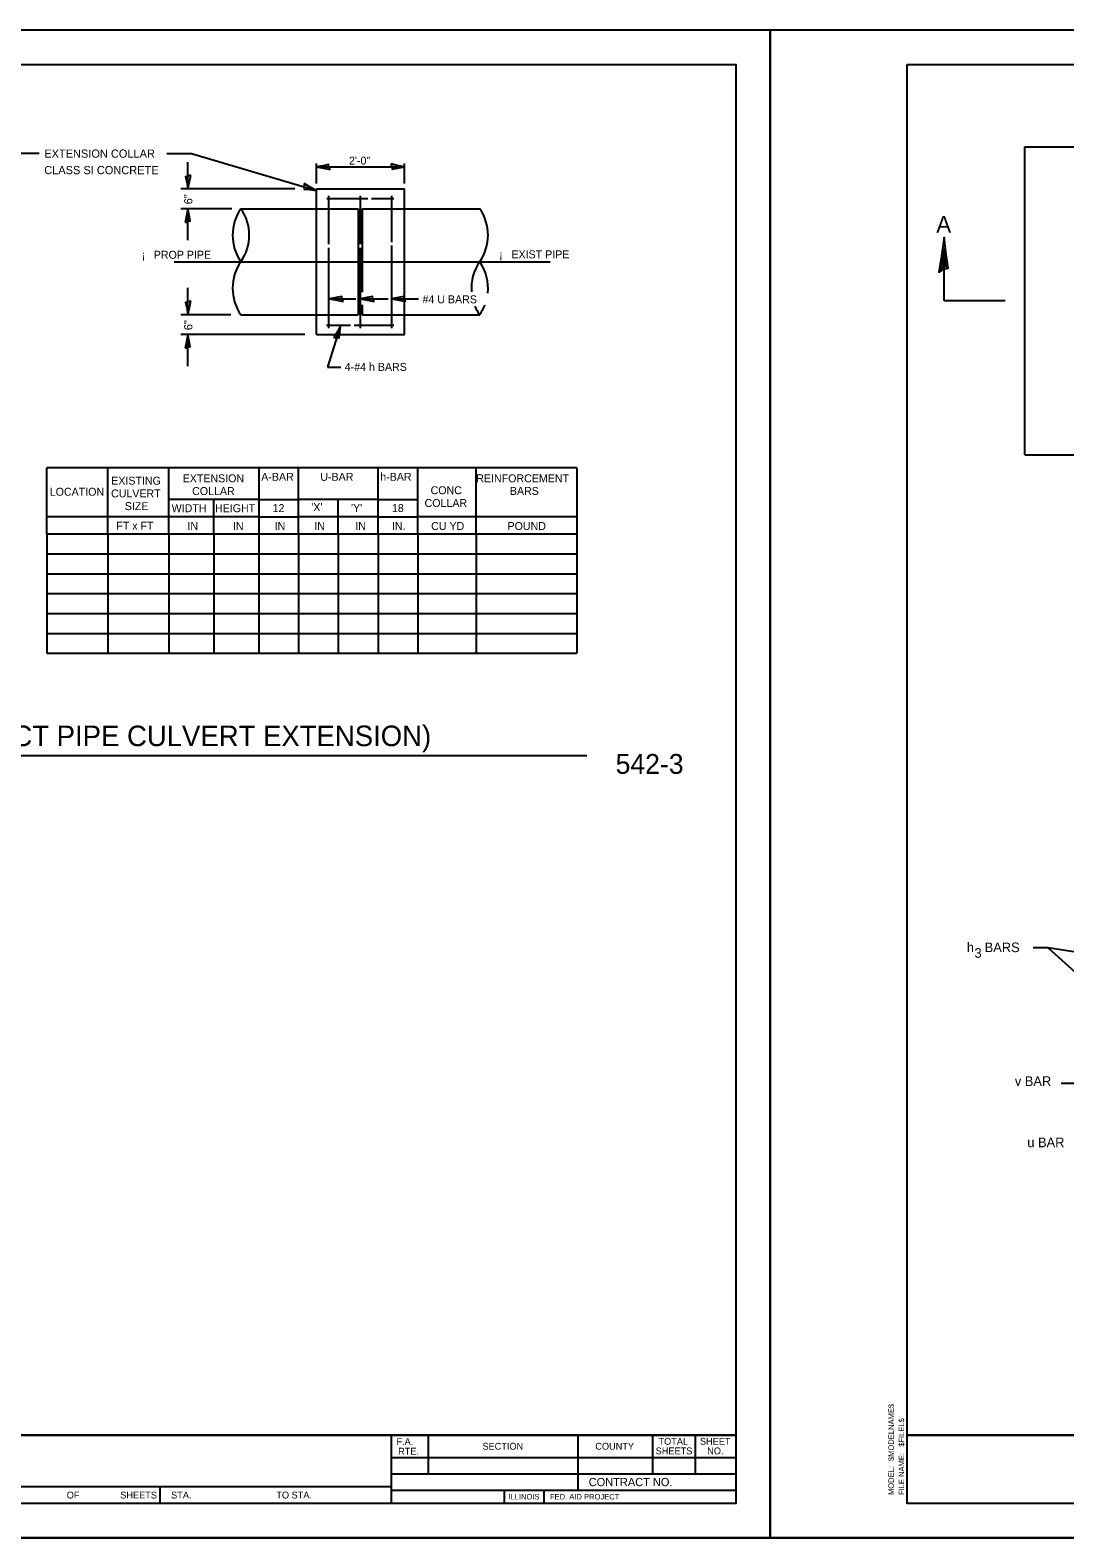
# Model space of a CAD drawing. Extents: x 2133490 to 2172050, y 2138301 to 2145980.
# Drawn here: x 2138050 to 2138805, y 2141438 to 2142538 of the extents above; entities that cross this region are included whole.
import ezdxf

# ---------------------------------------------------------------- set-up
doc = ezdxf.new("R2010")
doc.units = 0
for name, color, linetype in [('Level 1', 7, 'Continuous'), ('Level 23', 7, 'Continuous'), ('Level 40', 7, 'Continuous'), ('Level 63', 7, 'Continuous'), ('ROW_PR_Notes', 7, 'Continuous'), ('Sheets_50 Reference Boundary', 7, 'Continuous'), ('Sheets_General Details', 7, 'Continuous'), ('Sheets_Printer Plotting Border', 7, 'Continuous')]:
    doc.layers.add(name, color=color, linetype=linetype)

msp = doc.modelspace()

# ---------------------------------------------------------------- linework, layer by layer
at = {"layer": 'Level 23'}
for p, q in [((2138062.3, 2142170), (2138062.3, 2142218.3)), ((2138448.7, 2142218.3), (2138062.3, 2142218.3)), ((2138106.7, 2142170), (2138106.7, 2142218.3)), ((2138151.2, 2142170), (2138151.2, 2142218.3)), ((2138151.2, 2142218.3), (2138151.2, 2142218.3)), ((2138216.8, 2142218.3), (2138216.8, 2142083)), ((2138245.8, 2142170), (2138245.8, 2142218.3)), ((2138245.8, 2142218.3), (2138245.8, 2142218.3)), ((2138303.8, 2142170), (2138303.8, 2142218.3)), ((2138332.8, 2142170), (2138332.8, 2142218.3)), ((2138375.3, 2142170), (2138375.3, 2142218.3)), ((2138448.7, 2142218.3), (2138448.7, 2142083)), ((2138216.8, 2142195.1), (2138151.2, 2142195.1)), ((2138216.8, 2142195.1), (2138245.8, 2142195.1)), ((2138303.8, 2142195.1), (2138245.8, 2142195.1)), ((2138274.8, 2142170), (2138274.8, 2142195.1)), ((2138303.8, 2142195.1), (2138332.8, 2142195.1)), ((2138184, 2142170), (2138184, 2142194.7)), ((2138151.2, 2142182.5), (2138062.6, 2142182.5)), ((2138216.8, 2142182.5), (2138151.2, 2142182.5)), ((2138216.8, 2142182.5), (2138245.8, 2142182.5)), ((2138303.8, 2142182.5), (2138245.8, 2142182.5)), ((2138303.8, 2142182.5), (2138332.8, 2142182.5)), ((2138448.7, 2142182.5), (2138332.8, 2142182.5)), ((2138062.3, 2142170), (2138062.3, 2142083)), ((2138063.1, 2142170), (2138151.2, 2142170)), ((2138106.7, 2142170), (2138106.7, 2142083)), ((2138151.2, 2142170), (2138151.2, 2142083)), ((2138151.2, 2142170), (2138151.2, 2142083)), ((2138151.2, 2142170), (2138216.8, 2142170)), ((2138184, 2142170.2), (2138184, 2142083)), ((2138216.8, 2142170), (2138245.8, 2142170)), ((2138245.8, 2142170.8), (2138245.8, 2142083)), ((2138245.8, 2142170), (2138303.8, 2142170)), ((2138274.8, 2142170), (2138274.8, 2142083)), ((2138303.8, 2142170), (2138303.8, 2142083)), ((2138303.8, 2142170), (2138332.8, 2142170)), ((2138332.8, 2142170), (2138332.8, 2142083)), ((2138332.8, 2142170), (2138448.7, 2142170)), ((2138375.3, 2142170), (2138375.3, 2142083)), ((2138061.7, 2142155.5), (2138151.2, 2142155.5)), ((2138151.2, 2142155.5), (2138216.8, 2142155.5)), ((2138216.8, 2142155.5), (2138245.8, 2142155.5)), ((2138245.8, 2142155.5), (2138303.8, 2142155.5)), ((2138303.8, 2142155.5), (2138332.8, 2142155.5)), ((2138332.8, 2142155.5), (2138448.7, 2142155.5)), ((2138063.1, 2142141), (2138151.2, 2142141)), ((2138151.2, 2142141), (2138216.8, 2142141)), ((2138216.8, 2142141), (2138245.8, 2142141)), ((2138245.8, 2142141), (2138303.8, 2142141)), ((2138303.8, 2142141), (2138332.8, 2142141)), ((2138332.8, 2142141), (2138448.7, 2142141)), ((2138062.6, 2142126.5), (2138151.2, 2142126.5)), ((2138151.2, 2142126.5), (2138216.8, 2142126.5)), ((2138216.8, 2142126.5), (2138245.8, 2142126.5)), ((2138245.8, 2142126.5), (2138303.8, 2142126.5)), ((2138303.8, 2142126.5), (2138332.8, 2142126.5)), ((2138332.8, 2142126.5), (2138448.7, 2142126.5)), ((2138062.2, 2142112), (2138151.2, 2142112)), ((2138151.2, 2142112), (2138216.8, 2142112)), ((2138216.8, 2142112), (2138245.8, 2142112)), ((2138245.8, 2142112), (2138303.8, 2142112)), ((2138303.8, 2142112), (2138332.8, 2142112)), ((2138332.8, 2142112), (2138448.7, 2142112)), ((2138062.6, 2142097.5), (2138151.2, 2142097.5)), ((2138151.2, 2142097.5), (2138216.8, 2142097.5)), ((2138216.8, 2142097.5), (2138245.8, 2142097.5)), ((2138245.8, 2142097.5), (2138303.8, 2142097.5)), ((2138303.8, 2142097.5), (2138332.8, 2142097.5)), ((2138332.8, 2142097.5), (2138448.7, 2142097.5)), ((2138062.3, 2142083), (2138151.2, 2142083)), ((2138151.2, 2142083), (2138216.8, 2142083)), ((2138216.8, 2142083), (2138245.8, 2142083)), ((2138245.8, 2142083), (2138303.8, 2142083)), ((2138303.8, 2142083), (2138332.8, 2142083)), ((2138332.8, 2142083), (2138448.7, 2142083))]:
    msp.add_line(p, q, dxfattribs=at)
at = {"layer": 'Level 40'}
for p, q in [((2138258.8, 2142407.3), (2138289.4, 2142407.3)), ((2138289.4, 2142407.3), (2138289.4, 2142330)), ((2138292.3, 2142407.3), (2138377.9, 2142407.3)), ((2138292.3, 2142407.3), (2138292.3, 2142346.3)), ((2138155.2, 2142368.6), (2138429.2, 2142368.6)), ((2138258.8, 2142330), (2138289.4, 2142330)), ((2138292.3, 2142337.1), (2138292.3, 2142330)), ((2138292.3, 2142330), (2138377.9, 2142330))]:
    msp.add_line(p, q, dxfattribs=at)
at = {"layer": 'Level 63'}
for p, q in [((2138056.8, 2142447.6), (2138041.2, 2142447.6)), ((2138149.8, 2142447.6), (2138167.7, 2142447.6)), ((2138165.2, 2142421.8), (2138165.2, 2142441.3)), ((2138167.7, 2142447.6), (2138258.8, 2142420.7)), ((2138258.8, 2142425.8), (2138258.8, 2142440.4)), ((2138258.8, 2142437.9), (2138323, 2142437.9)), ((2138323, 2142425.8), (2138323, 2142440.4)), ((2138243.1, 2142421.8), (2138160, 2142421.8)), ((2138197.2, 2142407.3), (2138160, 2142407.3)), ((2138165.2, 2142384.3), (2138165.2, 2142407.3)), ((2138165.2, 2142330), (2138165.2, 2142349.6)), ((2138196.4, 2142330), (2138160, 2142330)), ((2138276.5, 2142322), (2138266.9, 2142291.6)), ((2138250.5, 2142315.5), (2138160, 2142315.5)), ((2138165.2, 2142292.5), (2138165.2, 2142315.5)), ((2138266.9, 2142291.6), (2138276.7, 2142291.6))]:
    msp.add_line(p, q, dxfattribs=at)
for points in [[(2138268.8, 2142435.8), (2138268, 2142437.7), (2138267.7, 2142439.5), (2138263.8, 2142438.7), (2138258.8, 2142437.9), (2138264.1, 2142436.9)], [(2138313, 2142440), (2138313.8, 2142438), (2138314.1, 2142436.2), (2138318, 2142437), (2138323, 2142437.9), (2138317.6, 2142438.8)], [(2138167.3, 2142431.8), (2138165.4, 2142431), (2138163.5, 2142430.6), (2138164.3, 2142426.8), (2138165.2, 2142421.8), (2138166.2, 2142427.1)], [(2138249.8, 2142425.6), (2138250, 2142423.5), (2138249.8, 2142421.6), (2138253.7, 2142421.3), (2138258.8, 2142420.7), (2138253.9, 2142423.2)], [(2138163.1, 2142397.3), (2138165, 2142398.1), (2138166.9, 2142398.4), (2138166.1, 2142402.3), (2138165.2, 2142407.3), (2138164.2, 2142402)], [(2138167.3, 2142340), (2138165.4, 2142339.2), (2138163.5, 2142338.9), (2138164.3, 2142335), (2138165.2, 2142330), (2138166.2, 2142335.3)], [(2138278.4, 2142339.5), (2138277.6, 2142341.4), (2138277.3, 2142343.3), (2138273.4, 2142342.5), (2138268.4, 2142341.6), (2138273.7, 2142340.6)], [(2138300.9, 2142339.5), (2138300.1, 2142341.4), (2138299.8, 2142343.3), (2138295.9, 2142342.5), (2138290.9, 2142341.6), (2138296.2, 2142340.6)], [(2138323.8, 2142339.5), (2138323, 2142341.4), (2138322.7, 2142343.3), (2138318.8, 2142342.5), (2138313.8, 2142341.6), (2138319.1, 2142340.6)], [(2138271.5, 2142313.1), (2138273.6, 2142313.3), (2138275.4, 2142313), (2138275.8, 2142317), (2138276.5, 2142322), (2138274, 2142317.2)], [(2138163.1, 2142305.5), (2138165, 2142306.3), (2138166.9, 2142306.7), (2138166.1, 2142310.5), (2138165.2, 2142315.5), (2138164.2, 2142310.2)]]:
    msp.add_lwpolyline(points, close=True, dxfattribs=at)
at = {"layer": 'ROW_PR_Notes'}
for p, q in [((2138775.4, 2142227.7), (2138775.4, 2142452.4)), ((2138775.4, 2142452.4), (2139621.5, 2142452.4)), ((2138258.8, 2142421.8), (2138323, 2142421.8)), ((2138258.8, 2142315.5), (2138258.8, 2142421.8)), ((2138268, 2142381.5), (2138268, 2142416.7)), ((2138290.9, 2142381.5), (2138290.9, 2142416.7)), ((2138313.8, 2142382.9), (2138313.8, 2142416.7)), ((2138323, 2142315.5), (2138323, 2142421.8)), ((2138203.8, 2142407.3), (2138258.8, 2142407.3)), ((2138266.5, 2142414.7), (2138296.4, 2142414.7)), ((2138299, 2142414.7), (2138315.3, 2142414.7)), ((2138268, 2142320.2), (2138268, 2142378.7)), ((2138290.9, 2142320.2), (2138290.9, 2142378.7)), ((2138313.8, 2142320.2), (2138313.8, 2142380.5)), ((2138716.5, 2142340.1), (2138716.5, 2142377.9)), ((2138268.4, 2142341.6), (2138287.7, 2142341.6)), ((2138290.9, 2142341.6), (2138311.2, 2142341.6)), ((2138313.8, 2142341.6), (2138333.3, 2142341.6)), ((2138761.1, 2142340.1), (2138716.5, 2142340.1)), ((2138203.8, 2142330), (2138258.8, 2142330)), ((2138266.1, 2142322.4), (2138283.7, 2142322.4)), ((2138286.3, 2142322.4), (2138315.3, 2142322.4)), ((2138258.8, 2142315.5), (2138323, 2142315.5)), ((2138775.4, 2142227.7), (2139621.5, 2142227.7)), ((2137804.4, 2142008.4), (2138455.9, 2142008.4)), ((2138792.3, 2141868.1), (2138781.4, 2141868.1)), ((2138853.2, 2141858.6), (2138792.3, 2141868.1)), ((2138792.3, 2141868.1), (2138854.1, 2141812.4)), ((2138823.4, 2141769.1), (2138802, 2141769.1))]:
    msp.add_line(p, q, dxfattribs=at)
msp.add_lwpolyline([(2138716.2, 2142363.2), (2138719.6, 2142364), (2138718.1, 2142373.8), (2138716.5, 2142386.4), (2138714.6, 2142372.9), (2138712.6, 2142361.1), (2138716.2, 2142363.2), (2138718.5, 2142364.2), (2138716.5, 2142377.9), (2138713.8, 2142362.9), (2138716.8, 2142365.2), (2138716.4, 2142371.5), (2138715.5, 2142365.4)], dxfattribs=at)
for centre, start, end in [((2138231.5, 2142388), 145.1049, 214.8951), ((2138176.1, 2142388), 325.1049, 34.8951), ((2138350.2, 2142388), 325.1049, 34.8951), ((2138231.5, 2142349.3), 145.1049, 214.8951), ((2138405.6, 2142349.3), 145.1049, 184.4399), ((2138350.2, 2142349.3), 353.7279, 34.8951), ((2138405.6, 2142349.3), 202.8569, 214.8951), ((2138350.2, 2142349.3), 325.1049, 338.936)]:
    msp.add_arc(centre, 33.8, start, end, dxfattribs=at)
at = {"layer": 'Sheets_50 Reference Boundary'}
for points in [[(2136989.7, 2142512.6), (2138564.7, 2142512.6), (2138564.7, 2141512.6), (2136989.7, 2141512.6)], [(2138689.7, 2142512.6), (2140264.7, 2142512.6), (2140264.7, 2141512.6), (2138689.7, 2141512.6)]]:
    msp.add_lwpolyline(points, close=True, dxfattribs=at)
at = {"layer": 'Sheets_General Details'}
for p, q in [((2138589.7, 2142537.6), (2136889.7, 2142537.6)), ((2138589.7, 2142537.6), (2138589.7, 2141437.6)), ((2140289.7, 2142537.6), (2138589.7, 2142537.6)), ((2138589.7, 2141437.6), (2138589.7, 2142537.6)), ((2136989.7, 2141512.6), (2138564.7, 2141512.6)), ((2138313.4, 2141512.6), (2138313.4, 2141462.6)), ((2138340.4, 2141512.6), (2138340.4, 2141484.3)), ((2138449.4, 2141512.6), (2138449.4, 2141472.3)), ((2138504, 2141512.6), (2138504, 2141484.3)), ((2138535, 2141512.6), (2138535, 2141484.3)), ((2138689.7, 2141512.6), (2140264.7, 2141512.6)), ((2138313.4, 2141496.3), (2138564.7, 2141496.3)), ((2138313.4, 2141484.3), (2138564.7, 2141484.3)), ((2137928.4, 2141475.1), (2138313.4, 2141475.1)), ((2138144.7, 2141475.1), (2138144.7, 2141462.6)), ((2138313.4, 2141472.3), (2138564.7, 2141472.3)), ((2138395.7, 2141472.3), (2138395.7, 2141462.6)), ((2138424.7, 2141472.3), (2138424.7, 2141462.6)), ((2138589.7, 2141437.6), (2136889.7, 2141437.6)), ((2140289.7, 2141437.6), (2138589.7, 2141437.6))]:
    msp.add_line(p, q, dxfattribs=at)
for points in [[(2136989.7, 2142512.6), (2138564.7, 2142512.6), (2138564.7, 2141462.6), (2136989.7, 2141462.6)], [(2138689.7, 2142512.6), (2140264.7, 2142512.6), (2140264.7, 2141462.6), (2138689.7, 2141462.6)]]:
    msp.add_lwpolyline(points, close=True, dxfattribs=at)
at = {"layer": 'Sheets_Printer Plotting Border'}
for points in [[(2136889.7, 2141437.6), (2138589.7, 2141437.6), (2138589.7, 2142537.6), (2136889.7, 2142537.6)], [(2138589.7, 2141437.6), (2140289.7, 2141437.6), (2140289.7, 2142537.6), (2138589.7, 2142537.6)]]:
    msp.add_lwpolyline(points, close=True, dxfattribs=at)

# ---------------------------------------------------------------- texts
at = {"layer": 'Level 1'}
msp.add_text('542-3', height=14.49, dxfattribs=at).set_placement((2138477, 2141995))
at = {"layer": 'Level 23'}
for s, height, p in [('EXISTING', 5.8, (2138109.2, 2142206)), ('EXTENSION', 5.8, (2138161.3, 2142207.7)), ('A-BAR', 5.8, (2138218.6, 2142208.8)), ('U-BAR', 5.8, (2138261.7, 2142208.8)), ('h-BAR', 5.8, (2138305.4, 2142208.8)), ('REINFORCEMENT', 5.8, (2138375.4, 2142207.7)), ('LOCATION', 5.8, (2138064.4, 2142197.9)), ('CULVERT', 5.8, (2138109.1, 2142196.7)), ('COLLAR', 5.8, (2138168.2, 2142198.4)), ('COLLAR', 5.8, (2138337.7, 2142189.7)), ('CONC', 5.8, (2138342.1, 2142199)), ('BARS', 5.8, (2138399.9, 2142198.5)), ('SIZE', 5.8, (2138119.1, 2142187.4)), ('WIDTH', 5.8, (2138153.3, 2142185.9)), ('HEIGHT', 5.8, (2138184.9, 2142185.9)), ('12', 5.8, (2138226.9, 2142186)), ('12', 5.8, (2138226.9, 2142186)), ("'X'", 5.8, (2138255.1, 2142186.7)), ("'Y'", 5.8, (2138284.1, 2142186.1)), ('18', 5.8, (2138313.9, 2142186)), ('FT x FT', 5.8, (2138112.9, 2142173.1)), ('IN', 5.8, (2138164.8, 2142172.9)), ('IN', 5.8, (2138198, 2142172.9)), ('IN', 5.8, (2138228.4, 2142172.9)), ('IN', 5.8, (2138257.3, 2142172.9)), ('IN', 5.8, (2138287.2, 2142172.9)), ('IN.', 5.8, (2138313.9, 2142172.9)), ('CU YD', 5.8, (2138342.5, 2142172.9)), ('POUND', 5.8, (2138398.2, 2142172.9)), ('COLLAR DETAIL (DIRECT PIPE CULVERT EXTENSION)', 15, (2137820.9, 2142015.2))]:
    msp.add_text(s, height=height, dxfattribs=at).set_placement(p)
at = {"layer": 'Level 63'}
for s, height, p in [('2\'-0"', 5.8, (2138282.6, 2142439.5)), ('#4 U BARS', 5.8, (2138336.2, 2142338.3)), ('4-#4 h BARS', 5.8, (2138279.5, 2142289)), ('h   BARS', 7, (2138733.1, 2141864.9)), ('3', 7, (2138738.7, 2141860.8)), ('v BAR', 7, (2138768.1, 2141767.3)), ('u BAR', 7, (2138777.2, 2141722.6))]:
    msp.add_text(s, height=height, dxfattribs=at).set_placement(p)
for p in [(2138168.4, 2142410.5), (2138168.4, 2142318.7)]:
    msp.add_text('6"', height=6, rotation=90, dxfattribs=at).set_placement(p)
at = {"layer": 'ROW_PR_Notes'}
for s, height, p in [('EXTENSION COLLAR', 6, (2138060.4, 2142444.5)), ('CLASS SI CONCRETE', 6, (2138060.4, 2142432.5)), ('A', 12.2, (2138710.8, 2142389.8)), ('¡', 5.8, (2138131.4, 2142370.8)), (' PROP PIPE', 5.8, (2138138.1, 2142370.8)), ('¡', 5.8, (2138392.1, 2142371.1)), (' EXIST PIPE', 5.8, (2138398.9, 2142371.1))]:
    msp.add_text(s, height=height, dxfattribs=at).set_placement(p)
at = {"layer": 'Sheets_General Details'}
for s, p in [('$MODELNAME$', (2138679.9, 2141493.6)), ('$FILEL$', (2138687.4, 2141504)), ('FILE NAME:', (2138687.4, 2141468.8)), ('MODEL:', (2138679.9, 2141468.8))]:
    msp.add_text(s, height=4, rotation=90, dxfattribs=at).set_placement(p)
for s, height, p in [('F.A.  ', 5, (2138317.2, 2141505.3)), ('RTE.', 5, (2138318.4, 2141498.3)), ('SECTION', 5, (2138379.9, 2141501.9)), ('COUNTY', 5, (2138462.2, 2141501.9)), ('SHEETS', 5, (2138506.2, 2141498.5)), ('TOTAL', 5, (2138508.3, 2141505.5)), ('SHEET', 5, (2138538.5, 2141505.5)), ('NO.', 5, (2138543.8, 2141498.5)), ('CONTRACT NO.      ', 6, (2138457.4, 2141475.3)), ('OF', 5, (2138076.8, 2141466.3)), ('SHEETS', 5, (2138115.8, 2141466.3)), ('STA.', 5, (2138152.9, 2141466.3)), ('TO STA.', 5, (2138229.6, 2141466.3)), ('ILLINOIS', 4, (2138398.8, 2141465.6)), ('FED. AID PROJECT', 4, (2138429.1, 2141465.6))]:
    msp.add_text(s, height=height, dxfattribs=at).set_placement(p)

doc.saveas('drawing.dxf')
